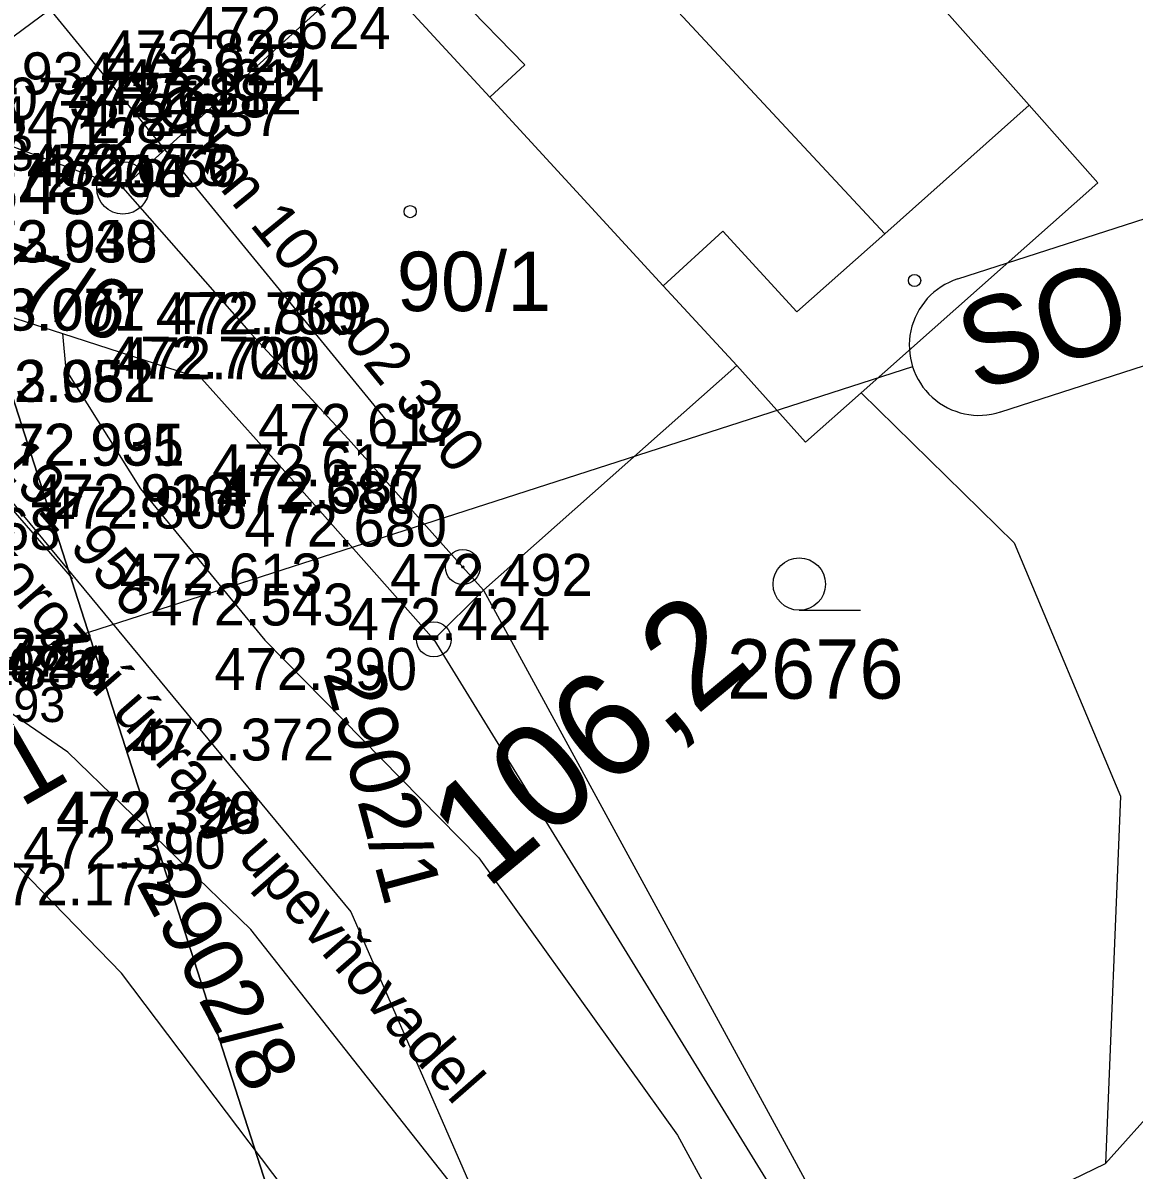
# Model space of a CAD drawing. Extents: x -758836 to -757729, y -1175316 to -1174366.
# Drawn here: x -758387.77 to -758355.96, y -1174869.02 to -1174836.19 of the extents above; entities that cross this region are included whole.
import ezdxf

# ---------------------------------------------------------------- set-up
doc = ezdxf.new("R2010")
doc.units = 0
for name, color, linetype in [('__NOR-dočasný zábor', 7, 'Continuous'), ('_NOR-pomocná', 7, 'Continuous'), ('_NOR-popis', 7, 'Continuous'), ('_vytyčený bod', 7, 'Continuous'), ('G_Obvod dráhy', 7, 'Continuous'), ('Hranice parcel', 7, 'Continuous'), ('Parcelní čísla', 7, 'Continuous'), ('Vnitřní kresba', 7, 'Continuous'), ('Vrstva 61', 7, 'Continuous'), ('Značky bodu BP', 7, 'Continuous'), ('Značky budov', 7, 'Continuous'), ('Značky kultur', 7, 'Continuous')]:
    doc.layers.add(name, color=color, linetype=linetype)

msp = doc.modelspace()

# ---------------------------------------------------------------- linework, layer by layer
at = {"layer": '_NOR-pomocná'}
for points in [[(-758417.595, -1174755.224), (-758317.652, -1174723.031), (-758272.123, -1174864.38), (-758372.066, -1174896.572)], [(-758517.538, -1174787.416), (-758417.595, -1174755.224), (-758372.066, -1174896.572), (-758472.009, -1174928.764)]]:
    msp.add_lwpolyline(points, close=True, dxfattribs=at)
at = {"layer": '_NOR-popis'}
for p, q in [((-758387.693, -1174834.949), (-758377.385, -1174847.55)), ((-758395.533, -1174841.585), (-758386.352, -1174852.094)), ((-758362.304, -1174846.032), (-758391.059, -1174855.295))]:
    msp.add_line(p, q, dxfattribs=at)
for points in [[(-758361.013, -1174843.516), (-758351.971, -1174840.603)], [(-758341.702, -1174841.498), (-758359.787, -1174847.323)]]:
    msp.add_lwpolyline(points, dxfattribs=at)
msp.add_arc((-758360.4, -1174845.419), 2, 107.8533, 287.854, dxfattribs=at)
at = {"layer": 'G_Obvod dráhy'}
msp.add_lwpolyline([(-758089.798, -1174768.979), (-758142.696, -1174770.56), (-758184.852, -1174773.129), (-758224.924, -1174775.568), (-758267.901, -1174783.224), (-758300.918, -1174790.499), (-758320.151, -1174797.166), (-758340.173, -1174807.597), (-758368.212, -1174821.896), (-758391.01, -1174838.771), (-758393.792, -1174842.868), (-758397.402, -1174848.189), (-758398.152, -1174849.288), (-758399.482, -1174851.258), (-758414.638, -1174865.002), (-758431.769, -1174880.634), (-758438.551, -1174887.875), (-758457.701, -1174908.335), (-758459.493, -1174910.255), (-758457.797, -1174912.615), (-758465.625, -1174912.295), (-758489.685, -1174938.02), (-758534.085, -1174974.005), (-758544.191, -1174980.324)], dxfattribs=at)
at = {"layer": 'Hranice parcel'}
for p, q in [((-758356.78, -1174868.83), (-758327.9, -1174836.41)), ((-758384.91, -1174840.91), (-758391.23, -1174838.56)), ((-758376.01, -1174853.83), (-758374.59, -1174852.42)), ((-758376.01, -1174853.83), (-758364.48, -1174872.56)), ((-758362.51, -1174871.59), (-758356.78, -1174868.83))]:
    msp.add_line(p, q, dxfattribs=at)
for points in [[(-758352.89, -1174817.05), (-758365.77, -1174824.68), (-758369.29, -1174826.9), (-758373.7, -1174830.81), (-758376.95, -1174833.7), (-758377.89, -1174834.53), (-758384.91, -1174840.91)], [(-758384.91, -1174840.91), (-758381.24, -1174845.09), (-758378.46, -1174848.09), (-758375.18, -1174851.76), (-758374.59, -1174852.42)], [(-758394.04, -1174842.7), (-758386.64, -1174845.08), (-758382.66, -1174846.36), (-758379.94, -1174849.4), (-758376.01, -1174853.83)], [(-758394.04, -1174842.7), (-758378.39, -1174861.63), (-758372.47, -1174875.16), (-758371.87, -1174876.54), (-758365.08, -1174901.85)], [(-758374.59, -1174852.42), (-758367.34, -1174845.99), (-758365.37, -1174848.19), (-758363.78, -1174846.77), (-758359.4, -1174851.07), (-758356.35, -1174858.32), (-758356.78, -1174868.83)], [(-758374.59, -1174852.42), (-758363.8, -1174872.21), (-758362.51, -1174871.59)], [(-758365.08, -1174901.85), (-758366.5, -1174900.55), (-758372.65, -1174883.97), (-758377.61, -1174873.09), (-758384.95, -1174863.38), (-758391.15, -1174857.01)]]:
    msp.add_lwpolyline(points, dxfattribs=at)
at = {"layer": 'Vnitřní kresba'}
for p, q in [((-758369.29, -1174826.9), (-758358.97, -1174838.54)), ((-758373.23, -1174831.34), (-758363.1, -1174842.22)), ((-758373.4, -1174837.39), (-758376.49, -1174834.22)), ((-758374.41, -1174838.31), (-758377.89, -1174834.53)), ((-758374.41, -1174838.31), (-758373.4, -1174837.39)), ((-758369.44, -1174843.71), (-758374.41, -1174838.31)), ((-758363.1, -1174842.22), (-758358.97, -1174838.54)), ((-758358.97, -1174838.54), (-758357, -1174840.76)), ((-758357, -1174840.76), (-758363.78, -1174846.77)), ((-758367.74, -1174842.15), (-758369.44, -1174843.71)), ((-758365.62, -1174844.46), (-758367.74, -1174842.15)), ((-758363.1, -1174842.22), (-758365.62, -1174844.46)), ((-758369.44, -1174843.71), (-758367.34, -1174845.99)), ((-758386.64, -1174845.08), (-758386.54, -1174846.12)), ((-758386.54, -1174846.12), (-758384.41, -1174849.52)), ((-758384.41, -1174849.52), (-758380.85, -1174853.85)), ((-758380.85, -1174853.85), (-758374.72, -1174860.08)), ((-758386.49, -1174857.06), (-758388.98, -1174855.35)), ((-758383.38, -1174860.07), (-758386.49, -1174857.06)), ((-758381.25, -1174862.13), (-758383.38, -1174860.07)), ((-758374.72, -1174860.08), (-758369.03, -1174868.02)), ((-758375.6, -1174869.3), (-758381.25, -1174862.13)), ((-758369.03, -1174868.02), (-758366.59, -1174872.52))]:
    msp.add_line(p, q, dxfattribs=at)
at = {"layer": 'Značky bodu BP'}
for centre, radius in [((-758384.91, -1174840.91), 0.75), ((-758384.91, -1174840.91), 0.03), ((-758375.18, -1174851.76), 0.5), ((-758375.18, -1174851.76), 0.0303), ((-758376.01, -1174853.83), 0.5), ((-758376.01, -1174853.83), 0.0303)]:
    msp.add_circle(centre, radius, dxfattribs=at)
at = {"layer": 'Značky budov'}
for centre in [(-758376.687, -1174841.589), (-758362.247, -1174843.559)]:
    msp.add_circle(centre, 0.175, dxfattribs=at)
at = {"layer": 'Značky kultur'}
msp.add_line((-758365.548, -1174852.997), (-758363.798, -1174852.997), dxfattribs=at)
msp.add_circle((-758365.548, -1174852.247), 0.75, dxfattribs=at)

# ---------------------------------------------------------------- texts
at = {"layer": '__NOR-dočasný zábor'}
msp.add_text('D1', height=2.2727, rotation=30, dxfattribs=at).set_placement((-758389.741, -1174859.768))
at = {"layer": '_NOR-popis'}
for s, height, rotation, p in [('ZO km 106,202 390', 1.25, 309.2844, (-758384.773, -1174837.728)), ('SO 11-13-01', 2.5, 17.854, (-758360.489, -1174846.761)), ('km 106,191 956', 1.25, 311.1419, (-758392.525, -1174844.268)), ('konec antikorozní úpravy upevňovadel', 1.25, 311.1419, (-758394.182, -1174845.716)), ('106,2', 3, 39.7421, (-758374.521, -1174861.028)), ('začátek antikorozní úpravy upevňovadel', 1.25, 312.9634, (-758403.709, -1174854.398))]:
    msp.add_text(s, height=height, rotation=rotation, dxfattribs=at).set_placement(p)
at = {"layer": '_vytyčený bod'}
for s, p in [('24', (-758389.173, -1174839.286)), ('23', (-758388.951, -1174840.419)), ('92', (-758388.169, -1174855.063)), ('93', (-758388.047, -1174856.196))]:
    msp.add_text(s, height=1, dxfattribs=at).set_placement(p)
at = {"layer": 'Parcelní čísla'}
for s, rotation, p in [('2677/6', 340, (-758391.627, -1174842.978)), ('2902/1', 285, (-758379.19, -1174854.777)), ('2902/8', 298, (-758384.551, -1174860.77))]:
    msp.add_text(s, height=1.7, rotation=rotation, dxfattribs=at).set_placement(p)
for s, p in [('90/1', (-758377.071, -1174844.435)), ('2676', (-758367.62, -1174855.527))]:
    msp.add_text(s, height=1.7, dxfattribs=at).set_placement(p)
at = {"layer": 'Vrstva 61'}
for s, p in [('472.624', (-758383.048, -1174836.934)), ('472.829', (-758385.448, -1174837.596)), ('472.627', (-758385.408, -1174837.973)), ('472.934', (-758390.931, -1174838.231)), ('472.614', (-758384.945, -1174838.427)), ('473.073', (-758391.359, -1174838.955)), ('472.618', (-758386.487, -1174838.892)), ('472.812', (-758385.589, -1174838.807)), ('472.847', (-758387.657, -1174839.623)), ('472.637', (-758386.083, -1174839.424)), ('473.012', (-758390.291, -1174840.096)), ('472.673', (-758387.667, -1174840.851)), ('472.750', (-758387.396, -1174840.875)), ('472.944', (-758388.886, -1174841.168)), ('472.906', (-758388.882, -1174841.167)), ('472.940', (-758389.743, -1174843.032)), ('473.038', (-758389.717, -1174843.043)), ('473.001', (-758390.078, -1174844.994)), ('473.077', (-758390.055, -1174844.99)), ('472.750', (-758383.97, -1174845.102)), ('472.809', (-758383.688, -1174845.091)), ('472.700', (-758385.309, -1174846.369)), ('472.729', (-758385.061, -1174846.384)), ('472.982', (-758389.813, -1174847.04)), ('473.051', (-758389.779, -1174847.031)), ('472.617', (-758381.046, -1174848.292)), ('472.935', (-758388.967, -1174848.86)), ('472.991', (-758388.942, -1174848.857)), ('472.617', (-758382.355, -1174849.446)), ('472.587', (-758382.108, -1174850.028)), ('472.836', (-758387.549, -1174850.325)), ('472.910', (-758387.531, -1174850.305)), ('472.680', (-758382.235, -1174850.227)), ('472.806', (-758387.156, -1174850.657)), ('472.968', (-758392.496, -1174851.269)), ('472.680', (-758381.433, -1174851.172)), ('472.613', (-758384.999, -1174852.573)), ('472.492', (-758377.26, -1174852.585)), ('472.543', (-758384.096, -1174853.432)), ('472.424', (-758378.474, -1174853.847)), ('472.828', (-758392.274, -1174854.711)), ('472.775', (-758391.501, -1174854.893)), ('472.874', (-758393.314, -1174855.135)), ('472.830', (-758391.104, -1174855.25)), ('472.744', (-758391.068, -1174855.208)), ('472.390', (-758382.29, -1174855.278)), ('472.372', (-758384.663, -1174857.296)), ('472.390', (-758386.819, -1174859.389)), ('472.328', (-758386.752, -1174859.388)), ('472.390', (-758387.771, -1174860.396)), ('472.173', (-758389.168, -1174861.437))]:
    msp.add_text(s, height=1.2, dxfattribs=at).set_placement(p)
at = {"layer": 'Značky bodu BP'}
msp.add_text('848', height=1.5, dxfattribs=at).set_placement((-758389.013, -1174841.66))

doc.saveas('drawing.dxf')
